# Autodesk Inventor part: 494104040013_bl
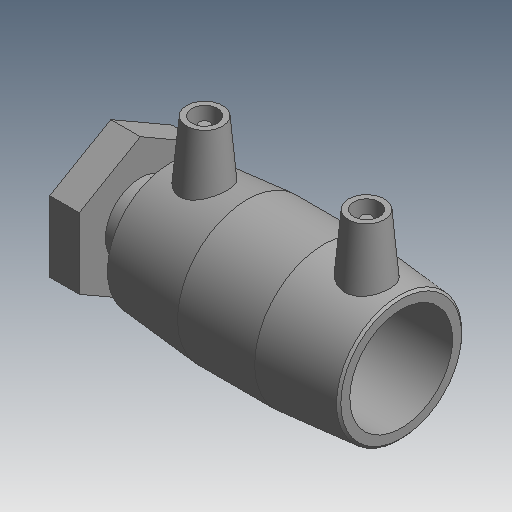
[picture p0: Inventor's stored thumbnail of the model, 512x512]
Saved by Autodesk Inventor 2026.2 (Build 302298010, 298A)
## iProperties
Created: 2017-06
Part Number: 494104040013_bl
Material: Generic
Description: PLASSON FEMALE FREE NUT TRANSITION COUPLER 40-1¼"
Document SubType Name: Modeling
Designer: KIM
Mass: 55.0731 g
Surface Area: 148.067 cm^2
Volume: 55.0731 cm^3
Density: 1 g/cm^3
Appearance: Default
Author: KIM
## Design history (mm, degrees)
derived "494104.ipt"
feature "Solid1::494104.ipt" dims "ScaleForDerivedMember" = 10
tag "TaggingFeature1"
body "Solid1"
other parameters: "d2" = 54 [user parameter], "d3" = 44 [user parameter], "d5" = 48.6 [user parameter], "d6" = 38 [user parameter], "d29" = 47 [user parameter], "d30" = 14 [user parameter], "d31" = 31.5 [user parameter], "d34" = 5 deg [user parameter], "d41" = 4 [user parameter], "d42" = 14 [user parameter], "d43" = 0 [user parameter], "d48" = 3 [user parameter], "d49" = 0 [user parameter], "d55" = 23 [user parameter], "d80" = 0.8 [user parameter], "d83" = 11.5 [user parameter], "d84" = 7.59 [user parameter], "d85" = 0.759 [user parameter], "d86" = 31.1616 [user parameter], "d87" = 38.952 [user parameter], "d88" = 41.952 [user parameter], "d89" = 54 [user parameter], "d96" = 27.2664 [user parameter], "d97" = 0 [user parameter], "d98" = 3.8952 [user parameter], "d99" = 3.8952 [user parameter], "d106" = 0 [user parameter], "d107" = 6.5 [user parameter], "L_" = 113 [user parameter], "L_1" = 44 [user parameter], "D_1" = 54 [user parameter], "A_" = 47 [user parameter], "d_2" = 12 [user parameter], "L_2" = 23 [user parameter], "D_" = 23 [user parameter], "G_" = 38.952 [user parameter], "d102" = 41.952 [user parameter]
